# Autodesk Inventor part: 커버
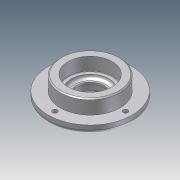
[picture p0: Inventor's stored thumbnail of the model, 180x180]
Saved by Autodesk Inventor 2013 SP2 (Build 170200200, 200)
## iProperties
Company: 한국ATC센터
Created: 2014-10
Part Number: 커버
Document SubType Name: Modeling
Designer: KYOUNG IL JANG
Density: 1 g/cm^3
Mass: 44.7286 g
Surface Area: 161.165 cm^2
Volume: 44.7286 cm^3
Material: 일반
Author: KYOUNG IL JANG
Revision Number: 1
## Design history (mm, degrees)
sketch "스케치1"
  geometry: C1 r 38 at (0, 0); 1 further point
  constraints: 1 centre point, 1 coincident
  dimensions: "d0" = 76 diameter of C1
extrude "돌출1" new body sketch "스케치1" distance "d1" = 7; taper "d2" = 0 deg
sketch "스케치2"
  geometry: C1 r 27 at (0, 0); 1 further point
  constraints: 1 centre point, 1 coincident
  dimensions: "d3" = 54 diameter of C1
extrude "돌출2" join sketch "스케치2" distance "d4" = 13; taper "d5" = 0 deg
sketch "스케치3"
  geometry: C1 r 20 at (0, 0); 1 further point
  constraints: 1 centre point, 1 coincident
  dimensions: "d6" = 40 diameter of C1
extrude "돌출3" join sketch "스케치3" distance "d7" = 5; taper "d8" = 0 deg
hole "구멍1" diameter "d11" = 25; stored, may be unused: countersink angle "d15" = 90 deg, drill point angle "d17" = 118 deg; dims "d9" = 10, "d10" = 10, "d12" = 6, "d13" = 32, "d14" = 8.3, "d16" = 8
hole "구멍2" diameter "d20" = 34; stored, may be unused: countersink angle "d24" = 90 deg, drill point angle "d26" = 0 deg; dims "d18" = 10, "d19" = 10, "d21" = 6, "d22" = 40, "d23" = 12, "d25" = 3
fillet "모깎기2" dims "d34" = 3
fillet "모깎기1" dims "d27" = 0.3
chamfer "모따기1" distance "d28" = 1; stored, may be unused: second distance "d29" = 2, angle "d30" = 45 deg
chamfer "모따기2" distance "d31" = 1.2; stored, may be unused: second distance "d32" = 2, angle "d33" = 30 deg
sketch "스케치4" dims "d35" = 64
  geometry: 3 further points
  constraints: 2 horizontal alignment, 1 coincident, 2 other
hole "구멍3" sketch "스케치4" at (32, 0) diameter "d36" = 4.5; stored, may be unused: countersink angle "d40" = 90 deg, drill point angle "d42" = 118 deg; dims "d37" = 6, "d38" = 8, "d39" = 4.4, "d41" = 13
node "솔리드1"
pattern_circular "원형 패턴1" dims angle "d44" = 360 deg
